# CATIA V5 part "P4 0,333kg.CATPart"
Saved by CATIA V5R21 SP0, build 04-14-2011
Part number: Part1.2
Material "Aluminium": density 2710 kg/m3, Young's modulus 7e+10 Pa, Poisson ratio 0.346, thermal expansion 2.36e-05 1/K
Bounding box of the stored display mesh (mm): x -50 to 50, y -19 to 19, z -55.516 to 44.484
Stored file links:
  C:\Users\HP\Desktop\Mes Fichiers\catia lesson\Mini Projet\Projet 1\P4 0,333kg.CATPart
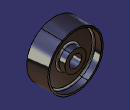
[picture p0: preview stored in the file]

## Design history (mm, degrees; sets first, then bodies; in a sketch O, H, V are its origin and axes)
AxisSystem1: origin (0, 0, 0), X (1, 0, 0), Y (0, 1, 0), Z (0, 0, 1)
Body1 (main body), material "Aluminium"
  Sketch1 on YZ plane of AxisSystem1, origin (0, 0, 0), H (0, 1, 0), V (0, 0, 1)
    line L1 (-19, -5.5161) -> (-19, 13.4839)
    line L2 (-19, 13.4839) -> (-5, 13.4839)
    line L3 (-5, 13.4839) -> (-5, 41.4839)
    line L4 (-5, 41.4839) -> (-19, 41.4839)
    point P5 (-19, 41.4839)
    line L5 (-19, 41.4839) -> (-19, 44.4839)
    line L6 (-19, 44.4839) -> (19, 44.4839)
    line L7 (19, 44.4839) -> (19, 41.4839)
    point P8 (19, 41.4839)
    line L8 (19, 41.4839) -> (5, 41.4839)
    line L9 (5, 41.4839) -> (5, 13.4839)
    point P10 (5, 13.4839)
    line L10 (5, 13.4839) -> (19, 13.4839)
    line L11 (19, 13.4839) -> (19, -5.5161)
    line L12 (19, -5.5161) -> (-19, -5.5161)
    reference intersected line E1 through (0, 0) direction (0, 1) from ZX plane of AxisSystem1
    axis line L13 (-64.681, -5.5161) -> (76.3595, -5.5161)
    point P13 (-64.681, -5.5161)
    length L6 = 38
    length L8 = 14
    length L4 = 14
    distance L11 L1 = 38
    distance L12 L2 = 19
    distance L6 L12 = 50
    length L7 = 3
    vertical: L1 V, L3 V, L5 V, L7 V, L9 V, L11 V
    horizontal: L2 H, L4 H, L6 H, L8 H, L10 H, L12 H, L13 H
    coincidence: P5 L1, P8 L4, P10 L2, P13 L12
    symmetry: L11 L1 E1
  Shaft1: profile Sketch1, axis Sketch1.L13, angle 360
  Fillet1: radius 3, on edge [face of Shaft1 from Sketch1.L3 | face of Shaft1 from Sketch1.L4]
  Sketch2 on face of Shaft1 from Sketch1.L1, origin (0, -19, 0), H (1, 0, 0), V (0, 0, 1)
    point P1 (0, -5.5161)
    reference projected circle E1 centre (0, -5.5161) radius 19 from edge [face of Shaft1 from Sketch1.L1 | face of Shaft1 from Sketch1.L2]
    concentricity: P1 E1
  Sketch3 on face of Shaft1 from Sketch1.L1, origin (0, -19, -5.5161), H (1, 0, 0), V (0, 0, 1)
    point P1 (0, 0)
    reference projected point E1 (0, 0) from Sketch2.P1
    coincidence: E1 P1
  Hole1: placed by Sketch3, at (0, -19, -5.5161) direction (0, 1, 0), diameter 22, through (limit type 3)
  Fillet2: radius 3, on face of Shaft1 from Sketch1.L9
